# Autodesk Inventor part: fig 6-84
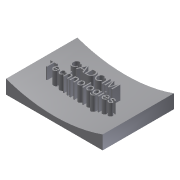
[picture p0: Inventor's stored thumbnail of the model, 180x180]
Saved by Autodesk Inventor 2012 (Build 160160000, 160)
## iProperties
Shininess: 64.0
Length Units: 11269
Angle Units: 11279
Time Units: 11290
Mass Units: 11283
Length Display Precision: 3
Angle Display Precision: 2
Compacted: True
Part Number: fig 6-84
Document SubType Name: Modeling
Created: 2002-12
Designer: deepak
Density: 1 g/cm^3
Material: Default
Density: 0.0
Volumn: 0.0
Area: 0.0
PropertySet Name: Model Information
Control State: 0
Master: False
Checked Out: False
Author: deepak
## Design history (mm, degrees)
sketch "Sketch1"
  geometry: L1 (-39.922, 33.786)-(30.103, 33.786); L2 (30.103, 33.786)-(30.103, -17.894); L3 (30.103, -17.894)-(-39.922, -17.894); L4 (-39.922, -17.894)-(-39.922, 33.786)
  constraints: 8 end point, 2 parallel, 1 horizontal, 1 perpendicular
extrude "Extrusion1" new body sketch "Sketch1" distance "d0" = 10; taper "d1" = 0 deg
workplane "Work Plane1"
sketch "Sketch2"
  geometry: L1 (-37.656, 15.034)-(26.28, 15.034); L2 (26.28, 15.034)-(26.28, 10.168); L3 (26.28, 10.168)-(-37.656, 10.168); L4 (-37.656, 10.168)-(-37.656, 15.034)
  constraints: 2 other
sketch "Sketch3"
  geometry: L1 (70.026, 10)-(0, 10) reference; A1 r 105 centre (35.013, 108.99) between (0, 10) and (70.026, 10)
  constraints: 2 point on circle, 1 centre point
  dimensions: "d5" = 105 radius of A1
extrude "Extrusion2" cut sketch "Sketch3" stored distance "d3" = 10; taper "d4" = 0 deg
emboss "Emboss4" sketch "Sketch2" dims "d14" = 1, "d15" = 0
body "Solid1"
other parameters: "d2" = 5
